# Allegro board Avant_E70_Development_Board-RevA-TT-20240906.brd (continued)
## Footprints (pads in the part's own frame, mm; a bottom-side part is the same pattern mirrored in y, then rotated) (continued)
TP
  round 1.4 hole 0.9: 1(0,0)
TP50
  round 1.524 hole 1.016: 1(0,0)
TP_50
  round 1.524 hole 1.016: 1(0,0)
TPC32
  round 0.813 smd: 1(0,0)
TQFN-14
  rect 0.84x0.3 smd: 1(-1.69,-0.75) 7(1.69,-0.75) 8(1.69,0.75) 14(-1.69,0.75)
  rect 0.3x0.84 smd: 2(-1,-1.69) 3(-0.5,-1.69) 4(0,-1.69) 5(0.5,-1.69) 6(1,-1.69) 9(1,1.69) 10(0.5,1.69) 11(0,1.69) 12(-0.5,1.69) 13(-1,1.69)
  rect 2.15x2.15 smd: 15(0,0)
TQFP64_0P5_12P2X12P2_H1P6
  rect 1.108x0.321 smd: 1(-5.8,3.75) 2(-5.8,3.25) 3(-5.8,2.75) 4(-5.8,2.25) 5(-5.8,1.75) 6(-5.8,1.25) 7(-5.8,0.75) 8(-5.8,0.25) 9(-5.8,-0.25) 10(-5.8,-0.75) 11(-5.8,-1.25) 12(-5.8,-1.75) 13(-5.8,-2.25) 14(-5.8,-2.75) 15(-5.8,-3.25) 16(-5.8,-3.75) 33(5.8,-3.75) 34(5.8,-3.25) 35(5.8,-2.75) 36(5.8,-2.25) 37(5.8,-1.75) 38(5.8,-1.25) 39(5.8,-0.75) 40(5.8,-0.25) 41(5.8,0.25) 42(5.8,0.75) 43(5.8,1.25) 44(5.8,1.75) 45(5.8,2.25) 46(5.8,2.75) 47(5.8,3.25) 48(5.8,3.75)
  rect 0.321x1.108 smd: 17(-3.75,-5.8) 18(-3.25,-5.8) 19(-2.75,-5.8) 20(-2.25,-5.8) 21(-1.75,-5.8) 22(-1.25,-5.8) 23(-0.75,-5.8) 24(-0.25,-5.8) 25(0.25,-5.8) 26(0.75,-5.8) 27(1.25,-5.8) 28(1.75,-5.8) 29(2.25,-5.8) 30(2.75,-5.8) 31(3.25,-5.8) 32(3.75,-5.8) 49(3.75,5.8) 50(3.25,5.8) 51(2.75,5.8) 52(2.25,5.8) 53(1.75,5.8) 54(1.25,5.8) 55(0.75,5.8) 56(0.25,5.8) 57(-0.25,5.8) 58(-0.75,5.8) 59(-1.25,5.8) 60(-1.75,5.8) 61(-2.25,5.8) 62(-2.75,5.8) 63(-3.25,5.8) 64(-3.75,5.8)
TSOT26_AP62201WU-7
  rect 1x0.7 smd: 1(-1.1,0.95) 2(-1.1,0) 3(-1.1,-0.95) 4(1.1,-0.95) 5(1.1,0) 6(1.1,0.95)
TUR_TH
  round 2.54 hole 1.956: 1(0,0)
UDFN6_040
  rect 0.22x0.42 smd: 1(-0.4,-0.325) 2(0,-0.325) 3(0.4,-0.325) 4(0.4,0.325) 5(0,0.325) 6(-0.4,0.325)
unnamed
  round 6.35 hole 4.089 unplated: (0,0)
USB_MINI_B-1734035-2
  round 0.9 hole 0.9 unplated: (-2.2,5.25) (2.2,5.25)
  rect 0.5x2.3 smd: 1(-1.6,7.85) 2(-0.8,7.85) 3(0,7.85) 4(0.8,7.85) 5(1.6,7.85)
  rect 2x2.5 smd: 6(-4.45,7.75) 7(-4.45,2.25) 8(4.45,2.25) 9(4.45,7.75)
USB_TYPEC_RA_SMT
  round 0.65 hole 0.65 unplated: (-3.6,1.04)
  oval 0.95x0.65 hole 0.95x0.65 unplated: (3.6,1.04)
  rect 0.3x0.7 smd: A1(-2.75,1.7) A2(-2.25,1.7) A3(-1.75,1.7) A4(-1.25,1.7) A5(-0.75,1.7) A6(-0.25,1.7) A7(0.25,1.7) A8(0.75,1.7) A9(1.25,1.7) A10(1.75,1.7) A11(2.25,1.7) A12(2.75,1.7) B1(2.5,0) B2(2,0) B3(1.5,0) B4(1,0) B5(0.5,0) B6(0,0) B7(-0.5,0) B8(-1,0) B9(-1.5,0) B10(-2,0) B11(-2.5,0) B12(-3,0)
  oval 1x1.6 hole 0.6x1.2: G1(-4.13,-0.21) G2(4.13,-0.21) G3(-4.49,-6.16) G4(4.49,-6.16)
X4-2520
  rect 1.2x1 smd: 1(-0.85,-0.65) 2(0.85,-0.65) 3(0.85,0.65) 4(-0.85,0.65)
XFDFN6
  rect 0.37x0.24 smd: 1(-0.515,0.4) 2(-0.515,0) 3(-0.515,-0.4) 4(0.515,-0.4) 5(0.515,0) 6(0.515,0.4)
  rect 0.4x1.08 smd: 7(0,0)
XTAL_4P_7M
  rect 1.4x1.2 smd: 1(-1.1,-0.85) 2(1.1,-0.85) 3(1.1,0.85) 4(-1.1,0.85)

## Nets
0V82_EN: R704.2 U45.C7(GPIO2) UNK0V82_EN.1
0V82_MON: R575.2 U45.K8(VMON1)
0V82_MON_GS: R576.2 U45.J8(VMON1GS)
0V82_TRIM: R562.2 U45.D8(TRIM1)
1V8_LDO: C208.1 FB16.1 FB28.1 R189.2 U116.5(VOUT)
1V80_EN: R716.2 U45.E6(GPIO4) UNK1V80_EN.1
1V80_MON: R577.2 U45.C10(VMON5) U45.J7(VMON3)
1V80_TRIM: R287.2 U45.B8(TRIM3)
12V00_MON: R289.1 R554.2 U45.B9(VMON9)
GND: C1.2 C2.2 C3.2 C4.2 C5.2 C6.2 C7.2 C8.2 C9.2 C10.2 C11.2 C12.2 C13.2 C14.2 C15.2 C16.2 C17.1 C18.1 C19.2 C20.2 C21.2 C22.2 C23.1 C24.2 C25.2 C26.2 C27.2 C29.1 C30.1 C31.2 C32.2 C33.2 C34.2 C36.2 C37.2 C38.2 C39.2 C40.2 C41.2 C42.2 C43.2 C44.2 C45.2 C46.2 C47.2 C49.2 C50.2 C51.2 C53.2 C54.2 C55.2 C56.2 C57.2 C58.2 C59.2 C60.2 C61.2 C63.2 C64.2 C65.2 C66.2 C69.2 C94.2 C97.2 C98.2 C99.2 C100.2 C103.2 C104.2 C113.2 C138.1 C139.1 C140.1 C142.2 C143.2 C144.2 C145.2 C146.2 C147.2 C148.2 C149.2 C150.2 C151.2 C152.2 C163.1 C164.2 C165.2 C166.2 C167.2 C168.1 C169.1 C171.2 C172.2 C173.2 C174.2 C175.2 C176.2 C177.2 C178.2 C207.2 C208.2 C287.2 C288.2 C289.2 C290.2 C291.2 C292.2 C293.2 C386.2 C387.2 C388.2 C396.2 C397.2 C398.2 C399.2 C400.2 C401.2 C402.1 C403.1 C404.2 C405.1 C465.2 C466.2 C467.2 C468.2 C469.2 C470.2 C471.2 C472.2 C473.2 C474.2 C475.2 C476.2 C477.2 C478.2 C479.2 C480.2 C481.2 C482.2 C483.2 C484.2 C485.2 C486.2 C487.2 C488.2 C489.2 C490.2 C491.2 C492.2 C493.2 C494.2 C495.2 C496.2 C497.2 C498.2 C499.2 C500.2 C501.2 C502.2 C503.2 C504.2 C505.2 C506.2 C507.2 C508.2 C509.2 C510.2 C511.2 C512.2 C525.2 C526.2 C527.2 C528.2 C529.2 C530.2 C531.2 C532.2 C533.2 C534.2 C535.2 C536.2 C537.2 C538.2 C539.2 C540.2 C541.2 C542.2 C543.2 C544.2 C545.2 C546.2 C547.2 C548.2 C556.2 C557.2 C558.2 C560.2 C561.2 C562.2 C563.2 C565.2 C579.2 C580.2 C584.2 C586.2 C587.2 C588.2 C589.2 C590.2 C591.2 C592.2 C593.2 C594.2 C595.2 C596.2 C597.2 C598.2 C599.2 C600.2 C612.2 C613.2 C614.2 C615.2 C616.2 C617.2 C618.2 C619.2 C620.1 C621.1 C622.2 C623.2 C625.2 C626.2 C628.2 C629.2 C630.2 C631.2 C632.2 C635.2 C636.2 C637.2 C639.2 C640.2 C641.2 C642.2 C643.2 C644.2 C646.2 C647.2 C648.2 C650.2 C651.2 C652.2 C654.2 C655.2 C656.2 C659.2 C660.2 C661.2 C663.2 C664.2 C665.2 C672.2 C673.2 C675.2 C676.2 C677.1 C713.2 C714.2 C717.2 C718.2 C719.2 C720.2 C721.2 C722.2 C723.2 C724.2 C725.2 C726.2 C727.2 C728.2 C729.2 C732.2 C733.2 C734.2 C1177.2 C1178.2 C1179.2 C1180.2 C1182.2 C1183.2 C1184.2 C1185.2 C1186.2 C1187.2 C1188.2 C1189.2 C1190.2 C1191.2 C1192.1 C1193.2 C1194.2 C1195.2 C1196.2 C1198.2 C1199.2 C1204.2 C1205.2 C1206.2 C1207.2 C1208.2 C1209.2 C1210.2 C1211.2 C1214.2 C1215.2 C1216.2 C1217.2 C1218.2 C1219.1 C1220.1 C1221.2 C1222.2 C1223.2 C1224.2 C1225.2 C1226.2 C1227.2 C1228.2 C1229.2 C1230.2 C1231.2 C1232.2 C1233.2 C1234.2 C1235.2 C1236.2 C1237.2 C1238.2 C1239.2 C1240.2 C1241.2 C1242.2 C1243.2 C1244.2 C1245.2 C1246.2 C1247.2 C1248.2 C1249.2 C1250.2 C1251.2 C1252.2 C1253.2 C1254.2 C1255.2 C1256.2 C1257.2 C1258.2 C1259.2 C1260.2 C1261.2 C1264.2 C1265.2 C1266.2 C1267.2 C1268.2 C1269.2 C1647.2 C1648.2 C1649.2 C1650.2 C1651.2 C1652.2 C1653.2 C1654.2 C1655.2 C1656.2 C1657.2 C1658.2 C1659.2 C1660.2 C1661.2 C1662.2 C1663.2 C1668.2 D1.K(CATHODE) D3.1(GND) D52.A1(ANODE1) D52.A2(ANODE2) D62.K D73.K D74.K D78.K GND1.1(TP) GND2.1(TP) GND3.1(TP) GND4.1(TP) GND5.1(TP) GND6.1(TP) GND7.1(TP) GND8.1(TP) GND9.1(TP) GND10.1(TP) GND11.1(TP) GND12.1(TP) GND13.1(TP) GND14.1(TP) GND15.1(TP) J1.7 J2.5(GND) J2.6(CASE#6) J2.7(CASE#7) J2.8(CASE#8) J2.9(CASE#9) J3.13 J3.14 J6.5 J6.11 J7.5 J7.11 J8.3 J10.11 J10.12 J25.A1(GND1) J25.A12(GND2) J25.B1(GND4) J25.B12(GND3) J25.G1(PGND1) J25.G2(PGND2) J25.G3(PGND3) J25.G4(PGND4) J31.1 J32.1 J33.1 J39.7 J48.A1(GND#A1) J48.A4(GND#A4) J48.A5(GND#A5) J48.A8(GND#A8) J48.A9(GND#A9) J48.A12(GND#A12) J48.A13(GND#A13) J48.A16(GND#A16) J48.A17(GND#A17) J48.A20(GND#A20) J48.A21(GND#A21) J48.A24(GND#A24) J48.A25(GND#A25) J48.A28(GND#A28) J48.A29(GND#A29) J48.A32(GND#A32) J48.A33(GND#A33) J48.A36(GND#A36) J48.A37(GND#A37) J48.A40(GND#A40) J48.B2(GND#B2) J48.B3(GND#B3) J48.B6(GND#B6) J48.B7(GND#B7) J48.B10(GND#B10) J48.B11(GND#B11) J48.B14(GND#B14) J48.B15(GND#B15) J48.B18(GND#B18) J48.B19(GND#B19) J48.B22(GND#B22) J48.B23(GND#B23) J48.B26(GND#B26) J48.B27(GND#B27) J48.B30(GND#B30) J48.B31(GND#B31) J48.B34(GND#B34) J48.B35(GND#B35) J48.B38(GND#B38) J48.B39(GND#B39) J48.C1(GND#C1) J48.C4(GND#C4) J48.C5(GND#C5) J48.C8(GND#C8) J48.C9(GND#C9) J48.C12(GND#C12) J48.C13(GND#C13) J48.C16(GND#C16) J48.C17(GND#C17) J48.C20(GND#C20) J48.C21(GND#C21) J48.C24(GND#C24) J48.C25(GND#C25) J48.C28(GND#C28) J48.C29(GND#C29) J48.C32(GND#C32) J48.C33(GND#C33) J48.C36(GND#C36) J48.C38(GND#C38) J48.C40(GND#C40) J48.D2(GND#D2) J48.D3(GND#D3) J48.D6(GND#D6) J48.D7(GND#D7) J48.D10(GND#D10) J48.D13(GND#D13) J48.D16(GND#D16) J48.D19(GND#D19) J48.D22(GND#D22) J48.D25(GND#D25) J48.D28(GND#D28) J48.D37(GND#D37) J48.D39(GND#D39) J48.E1(GND#E1) J48.E4(GND#E4) J48.E5(GND#E5) J48.E8(GND#E8) J48.E11(GND#E11) J48.E14(GND#E14) J48.E17(GND#E17) J48.E20(GND#E20) J48.E23(GND#E23) J48.E26(GND#E26) J48.E29(GND#E29) J48.E32(GND#E32) J48.E35(GND#E35) J48.E38(GND#E38) J48.E40(GND#E40) J48.F2(GND#F2) J48.F3(GND#F3) J48.F6(GND#F6) J48.F9(GND#F9) J48.F12(GND#F12) J48.F15(GND#F15) J48.F18(GND#F18) J48.F21(GND#F21) J48.F24(GND#F24) J48.F27(GND#F27) J48.F30(GND#F30) J48.F33(GND#F33) J48.F36(GND#F36) J48.F39(GND#F39) J48.G1(GND#G1) J48.G4(GND#G4) J48.G5(GND#G5) J48.G8(GND#G8) J48.G11(GND#G11) J48.G14(GND#G14) J48.G17(GND#G17) J48.G20(GND#G20) J48.G23(GND#G23) J48.G26(GND#G26) J48.G29(GND#G29) J48.G32(GND#G32) J48.G35(GND#G35) J48.G38(GND#G38) J48.G40(GND#G40) J48.H3(GND#H3) J48.H6(GND#H6) J48.H9(GND#H9) J48.H12(GND#H12) J48.H15(GND#H15) J48.H18(GND#H18) J48.H21(GND#H21) J48.H24(GND#H24) J48.H27(GND#H27) J48.H30(GND#H30) J48.H33(GND#H33) J48.H36(GND#H36) J48.H39(GND#H39) J48.J1(GND#J1) J48.J4(GND#J4) J48.J5(GND#J5) J48.J8(GND#J8) J48.J11(GND#J11) J48.J14(GND#J14) J48.J17(GND#J17) J48.J20(GND#J20) J48.J23(GND#J23) J48.J26(GND#J26) J48.J29(GND#J29) J48.J32(GND#J32) J48.J35(GND#J35) J48.J38(GND#J38) J48.J40(GND#J40) J48.K2(GND#K2) J48.K3(GND#K3) J48.K6(GND#K6) J48.K9(GND#K9) J48.K12(GND#K12) J48.K15(GND#K15) J48.K18(GND#K18) J48.K21(GND#K21) J48.K24(GND#K24) J48.K27(GND#K27) J48.K30(GND#K30) J48.K33(GND#K33) J48.K36(GND#K36) J48.K39(GND#K39) J50.2(GND#2) J50.3(GND#3) J53.11 J53.12 J54.A1(GND#A1) J54.A4(GND#A4) J54.A5(GND#A5) J54.A8(GND#A8) J54.A9(GND#A9) J54.A12(GND#A12) J54.A13(GND#A13) J54.A16(GND#A16) J54.A17(GND#A17) J54.A20(GND#A20) J54.A21(GND#A21) J54.A24(GND#A24) J54.A25(GND#A25) J54.A28(GND#A28) J54.A29(GND#A29) J54.A32(GND#A32) J54.A33(GND#A33) J54.A36(GND#A36) J54.A37(GND#A37) J54.A40(GND#A40) J54.B2(GND#B2) J54.B3(GND#B3) J54.B6(GND#B6) J54.B7(GND#B7) J54.B10(GND#B10) J54.B11(GND#B11) J54.B14(GND#B14) J54.B15(GND#B15) J54.B18(GND#B18) J54.B19(GND#B19) J54.B22(GND#B22) J54.B23(GND#B23) J54.B26(GND#B26) J54.B27(GND#B27) J54.B30(GND#B30) J54.B31(GND#B31) J54.B34(GND#B34) J54.B35(GND#B35) J54.B38(GND#B38) J54.B39(GND#B39) J54.C1(GND#C1) J54.C4(GND#C4) J54.C5(GND#C5) J54.C8(GND#C8) J54.C9(GND#C9) J54.C12(GND#C12) J54.C13(GND#C13) J54.C16(GND#C16) J54.C17(GND#C17) J54.C20(GND#C20) J54.C21(GND#C21) J54.C24(GND#C24) J54.C25(GND#C25) J54.C28(GND#C28) J54.C29(GND#C29) J54.C32(GND#C32) J54.C33(GND#C33) J54.C36(GND#C36) J54.C38(GND#C38) J54.C40(GND#C40) J54.D2(GND#D2) J54.D3(GND#D3) J54.D6(GND#D6) J54.D7(GND#D7) J54.D10(GND#D10) J54.D13(GND#D13) J54.D16(GND#D16) J54.D19(GND#D19) J54.D22(GND#D22) J54.D25(GND#D25) J54.D28(GND#D28) J54.D37(GND#D37) J54.D39(GND#D39) J54.E1(GND#E1) J54.E4(GND#E4) J54.E5(GND#E5) J54.E8(GND#E8) J54.E11(GND#E11) J54.E14(GND#E14) J54.E17(GND#E17) J54.E20(GND#E20) J54.E23(GND#E23) J54.E26(GND#E26) J54.E29(GND#E29) J54.E32(GND#E32) J54.E35(GND#E35) J54.E38(GND#E38) J54.E40(GND#E40) J54.F2(GND#F2) J54.F3(GND#F3) J54.F6(GND#F6) J54.F9(GND#F9) J54.F12(GND#F12) J54.F15(GND#F15) J54.F18(GND#F18) J54.F21(GND#F21) J54.F24(GND#F24) J54.F27(GND#F27) J54.F30(GND#F30) J54.F33(GND#F33) J54.F36(GND#F36) J54.F39(GND#F39) J54.G1(GND#G1) J54.G4(GND#G4) J54.G5(GND#G5) J54.G8(GND#G8) J54.G11(GND#G11) J54.G14(GND#G14) J54.G17(GND#G17) J54.G20(GND#G20) J54.G23(GND#G23) J54.G26(GND#G26) J54.G29(GND#G29) J54.G32(GND#G32) J54.G35(GND#G35) J54.G38(GND#G38) J54.G40(GND#G40) J54.H3(GND#H3) J54.H6(GND#H6) J54.H9(GND#H9) J54.H12(GND#H12) J54.H15(GND#H15) J54.H18(GND#H18) J54.H21(GND#H21) J54.H24(GND#H24) J54.H27(GND#H27) J54.H30(GND#H30) J54.H33(GND#H33) J54.H36(GND#H36) J54.H39(GND#H39) J54.J1(GND#J1) J54.J4(GND#J4) J54.J5(GND#J5) J54.J8(GND#J8) J54.J11(GND#J11) J54.J14(GND#J14) J54.J17(GND#J17) J54.J20(GND#J20) J54.J23(GND#J23) J54.J26(GND#J26) J54.J29(GND#J29) J54.J32(GND#J32) J54.J35(GND#J35) J54.J38(GND#J38) J54.J40(GND#J40) J54.K2(GND#K2) J54.K3(GND#K3) J54.K6(GND#K6) J54.K9(GND#K9) J54.K12(GND#K12) J54.K15(GND#K15) J54.K18(GND#K18) J54.K21(GND#K21) J54.K24(GND#K24) J54.K27(GND#K27) J54.K30(GND#K30) J54.K33(GND#K33) J54.K36(GND#K36) J54.K39(GND#K39) J81.1 J83.13 JP3.2 JP15.1 JP17.2 JP26.6 JP26.9 JP26.14 JP26.20 JP26.25 JP26.30 JP26.34 JP26.39 JP64.2 Q1.E(EMITTER) Q2.E Q3.E Q4.E Q7.E Q8.E Q9.E Q10.E Q11.E Q12.E Q13.E Q14.E Q15.E Q16.E Q17.E Q18.E Q19.E Q20.E Q21.E Q22.E Q23.E Q24.E Q26.S Q27.E Q28.E Q29.E Q30.E Q31.E Q32.E Q33.E Q34.E R5.2 R15.1 R54.1 R77.2 R92.2 R95.1 R100.2 R180.2 R192.1 R232.2 R234.2 R245.2 R251.1 R252.1 R306.2 R307.1 R317.2 R325.1 R326.1 R340.2 R342.2 R344.2 R398.2 R401.1 R406.1 R413.2 R415.2 R419.2 R421.2 R424.2 R429.2 R430.2 R435.2 R436.2 R440.2 R442.2 R449.2 R451.2 R455.2 R457.2 R465.2 R466.1 R493.1 R545.2 R548.1 R554.1 R568.2 R569.2 R576.1 R583.1 R589.2 R596.2 R597.1 R598.1 R611.1 R612.1 R613.1 R614.1 R616.1 R617.1 R620.2 R621.2 R625.2 R629.2 R639.1 R641.2 R642.2 R643.2 R644.1 R645.1 R651.2 R652.2 R653.2 R654.2 R655.2 R656.2 R663.2 R664.2 R665.2 R666.2 R667.2 R668.2 R669.1 R670.1 R671.1 R672.1 R673.1 R674.1 R681.1 R686.2 R696.2 R697.2 R703.1 SW1.1(A1) SW1.3(A2) SW2.1(A1) SW2.3(A2) SW3.9(B8) SW3.10(B7) SW3.11(B6) SW3.12(B5) SW3.13(B4) SW3.14(B3) SW3.15(B2) SW3.16(B1) SW4.1(A1) SW4.3(A2) SW5.1(A1) SW5.3(A2) SW8.1(A1) SW8.3(A2) U1.1(GND#1) U1.5(GND#5) U1.10(AGND) U1.11(GND#11) U1.13(TEST) U1.15(GND#15) U1.25(GND#25) U1.35(GND#35) U1.47(GND#47) U1.51(GND#51) U2.5(VSS) U3.A1(VSS#A1) U3.A2(VSS#A2) U3.A3(VSS#A3) U3.A4(VSS#A4) U3.A7(VSS#A7) U3.A10(VSS#A10) U3.A13(VSS#A13) U3.A16(VSS#A16) U3.A19(VSS#A19) U3.A22(VSS#A22) U3.A25(VSS#A25) U3.A28(VSS#A28) U3.A31(VSS#A31) U3.A34(VSS#A34) U3.AA6(VSS#AA6) U3.AB2(VSS#AB2) U3.AB8(VSS#AB8) U3.AB11(VSS#AB11) U3.AB23(VSS#AB23) U3.AC18(VSS#AC18) U3.AC22(VSS#AC22) U3.AC32(VSS#AC32) U3.AD13(VSS#AD13) U3.AD25(VSS#AD25) U3.AD28(VSS#AD28) U3.AE16(VSS#AE16) U3.AF8(VSS#AF8) U3.AG3(VSS#AG3) U3.AG22(VSS#AG22) U3.AH11(VSS#AH11) U3.AH19(VSS#AH19) U3.AH28(VSS#AH28) U3.AH32(VSS#AH32) U3.AJ8(VSS#AJ8) U3.AJ14(VSS#AJ14) U3.AJ25(VSS#AJ25) U3.AL3(VSS#AL3) U3.AL32(VSS#AL32) U3.AM7(VSS#AM7) U3.AM12(VSS#AM12) U3.AM15(VSS#AM15) U3.AM19(VSS#AM19) U3.AM22(VSS#AM22) U3.AN27(VSS#AN27) U3.AP1(VSS#AP1) U3.AP34(VSS#AP34) U3.B2(VSS#B2) U3.B4(VSS#B4) U3.B5(VSS#B5) U3.B6(VSS#B6) U3.B7(VSSR#B7) U3.B8(VSS#B8) U3.B9(VSS#B9) U3.B10(VSSR#B10) U3.B11(VSS#B11) U3.B12(VSS#B12) U3.B13(VSSR#B13) U3.B14(VSS#B14) U3.B15(VSS#B15) U3.B16(VSSR#B16) U3.B17(VSS#B17) U3.B18(VSS#B18) U3.B19(VSSR#B19) U3.B20(VSS#B20) U3.B21(VSS#B21) U3.B22(VSSR#B22) U3.B23(VSS#B23) U3.B24(VSS#B24) U3.B25(VSSR#B25) U3.B26(VSS#B26) U3.B27(VSS#B27) U3.B28(VSSR#B28) U3.B29(VSS#B29) U3.B30(VSS#B30) U3.B31(VSSR#B31) U3.B32(VSS#B32) U3.B33(VSS#B33) U3.B34(VSSR#B34) U3.C2(VSS#C2) U3.C4(VSS#C4) U3.C7(VSS#C7) U3.C10(VSS#C10) U3.C13(VSS#C13) U3.C16(VSS#C16) U3.C19(VSS#C19) U3.C22(VSS#C22) U3.C25(VSS#C25) U3.C28(VSS#C28) U3.C31(VSS#C31) U3.C34(VSS#C34) U3.D1(VSS#D1) U3.D2(VSSR#D2) U3.D3(VSS#D3) U3.D4(VSSR#D4) U3.D5(VSS#D5) U3.D6(VSS#D6) U3.D7(VSSR#D7) U3.D8(VSS#D8) U3.D9(VSS#D9) U3.D10(VSSR#D10) U3.D11(VSS#D11) U3.D12(VSS#D12) U3.D13(VSSR#D13) U3.D14(VSS#D14) U3.D15(VSS#D15) U3.D16(VSSR#D16) U3.D17(VSS#D17) U3.D18(VSS#D18) U3.D19(VSSR#D19) U3.D20(VSS#D20) U3.D21(VSS#D21) U3.D22(VSSR#D22) U3.D23(VSS#D23) U3.D24(VSS#D24) U3.D25(VSSR#D25) U3.D26(VSS#D26) U3.D27(VSS#D27) U3.D28(VSSR#D28) U3.D29(VSS#D29) U3.D30(VSS#D30) U3.D31(VSSR#D31) U3.D32(VSS#D32) U3.D33(VSS#D33) U3.D34(VSSR#D34) U3.E2(VSS#E2) U3.E4(VSS#E4) U3.E7(VSS#E7) U3.E10(VSS#E10) U3.E13(VSS#E13) U3.E16(VSS#E16) U3.E19(VSS#E19) U3.E22(VSS#E22) U3.E25(VSS#E25) U3.E28(VSS#E28) U3.E31(VSS#E31) U3.E34(VSS#E34) U3.F2(VSS#F2) U3.F4(VSS#F4) U3.F5(VSS#F5) U3.F6(VSS#F6) U3.F7(VCCJB#F7) U3.F8(VSS#F8) U3.F9(VSS#F9) U3.F10(VCCJB#F10) U3.F11(VSS#F11) U3.F12(VSS#F12) U3.F13(VCCJB#F13) U3.F14(VSS#F14) U3.F15(VSS#F15) U3.F16(VCCJB#F16) U3.F17(VSS#F17) U3.F18(VSS#F18) U3.F19(VCCJB#F19) U3.F20(VSS#F20) U3.F21(VSS#F21) U3.F22(VCCJB#F22) U3.F23(VSS#F23) U3.F24(VSS#F24) U3.F25(VCCJB#F25) U3.F26(VSS#F26) U3.F27(VSS#F27) U3.F28(VCCJB#F28) U3.F29(VSS#F29) U3.F30(VSS#F30) U3.F31(VCCJB#F31) U3.F32(VSS#F32) U3.F33(VSS#F33) U3.F34(VCCJB#F34) U3.G1(VSS#G1) U3.G2(VSSR#G2) U3.G3(VSS#G3) U3.G4(VSSR#G4) U3.G7(VSS#G7) U3.G10(VSS#G10) U3.G13(VSS#G13) U3.G16(VSS#G16) U3.G19(VSS#G19) U3.G22(VSS#G22) U3.G25(VSS#G25) U3.G28(VSS#G28) U3.G31(VSS#G31) U3.G34(VSS#G34) U3.H2(VSS#H2) U3.H4(VSS#H4) U3.H5(VSS#H5) U3.H6(VSS#H6) U3.H7(VCCJB#H7) U3.H8(VSS#H8) U3.H9(VSS#H9) U3.H10(VCCJB#H10) U3.H11(VSS#H11) U3.H12(VSS#H12) U3.H13(VCCJB#H13) U3.H14(VSS#H14) U3.H15(VSS#H15) U3.H16(VCCJB#H16) U3.H17(VSS#H17) U3.H18(VSS#H18) U3.H19(VCCJB#H19) U3.H20(VSS#H20) U3.H21(VSS#H21) U3.H22(VCCJB#H22) U3.H23(VSS#H23) U3.H24(VSS#H24) U3.H25(VCCJB#H25) U3.H26(VSS#H26) U3.H27(VSS#H27) U3.H28(VCCJB#H28) U3.H29(VSS#H29) U3.H30(VSS#H30) U3.H31(VCCJB#H31) U3.H32(VSS#H32) U3.H33(VSS#H33) U3.H34(VCCJB#H34) U3.J2(VSS#J2) U3.J4(VSS#J4) U3.J5(VSS#J5) U3.J7(VSS#J7) U3.J8(VSSR#J8) U3.J9(VSSR#J9) U3.J10(VSS#J10) U3.J11(VSSR#J11) U3.J13(VSS#J13) U3.J14(VSSR#J14) U3.J15(VSSR#J15) U3.J16(VSS#J16) U3.J17(VCCJB#J17) U3.J19(VSS#J19) U3.J20(VSSR#J20) U3.J21(VSSR#J21) U3.J22(VSS#J22) U3.J23(VSS#J23) U3.J25(VSS#J25) U3.J26(VSSR#J26) U3.J27(VSSR#J27) U3.J28(VSS#J28) U3.J29(VSSR#J29) U3.J31(VSS#J31) U3.J32(VSSR#J32) U3.J33(VSSR#J33) U3.J34(VSS#J34) U3.K1(VSS#K1) U3.K2(VCCJB#K2) U3.K3(VSS#K3) U3.K4(VCCJB#K4) U3.K5(VSSR#K5) U3.K6(VSS#K6) U3.K7(VSSR#K7) U3.K8(VSS#K8) U3.K9(VSS#K9) U3.K10(VCCJB#K10) U3.K11(VSS#K11) U3.K12(VCCJB#K12) U3.K13(VCCJB#K13) U3.K14(VSS#K14) U3.K15(VSS#K15) U3.K16(VCCJB#K16) U3.K17(VSS#K17) U3.K18(VSS#K18) U3.K19(VSSR#K19) U3.K20(VSS#K20) U3.K21(VSS#K21) U3.K22(VCCJB#K22) U3.K23(VSS#K23) U3.K24(VSS#K24) U3.K25(VCCJB#K25) U3.K26(VSS#K26) U3.K27(VSS#K27) U3.K28(VSS#K28) U3.K29(VCCJB#K29) U3.K30(VSS#K30) U3.K31(VSS#K31) U3.K32(VSS#K32) U3.K33(VSS#K33) U3.K34(VSS#K34) U3.L2(VSS#L2) U3.L4(VSS#L4) U3.L5(VSSR#L5) U3.L6(VCCJB#L6) U3.L13(VSSR#L13) U3.L14(VSSR#L14) U3.L15(VSSR#L15) U3.L16(VCCJB#L16) U3.L17(VSSR#L17) U3.L18(VCCJB#L18) U3.L19(VSS#L19) U3.L20(VCCJB#L20) U3.L21(VSS#L21) U3.L22(VSSR#L22) U3.L23(VSS#L23) U3.L24(VSSR#L24) U3.L25(VSS#L25) U3.L27(VSS#L27) U3.L29(VSS#L29) U3.L31(VSS#L31) U3.L33(VSS#L33) U3.M2(VSS#M2) U3.M4(VSS#M4) U3.M5(VSS#M5) U3.M11(VSS#M11) U3.M15(VSS#M15) U3.M17(VSS#M17) U3.M18(VSS#M18) U3.M21(VCCJB#M21) U3.M22(VSS#M22) U3.M23(VCCJB#M23) U3.M24(VSS#M24) U3.M25(VCCJB#M25) U3.M26(VSS#M26) U3.M27(VSS#M27) U3.M29(VSS#M29) U3.M31(VSS#M31) U3.M33(VSS#M33) U3.N1(VSS#N1) U3.N2(VCCJB#N2) U3.N3(VSS#N3) U3.N4(VCCJB#N4) U3.N9(VSS#N9) U3.N13(VSS#N13) U3.N23(VSS#N23) U3.N25(VSS#N25) U3.N26(VSSR#N26) U3.N27(VCCJB#N27) U3.N28(VSS#N28) U3.N29(VCCJB#N29) U3.N30(VSS#N30) U3.N31(VSSR#N31) U3.N32(VSS#N32) U3.N33(VSSR#N33) U3.N34(VSS#N34) U3.P17(VSS#P17) U3.P22(VSS#P22) U3.P23(VSSR#P23) U3.P24(VSS#P24) U3.P25(VCCJB#P25) U3.P26(VSSR#P26) U3.P27(VSS#P27) U3.P29(VSS#P29) U3.P31(VSS#P31) U3.P33(VSS#P33) U3.R21(VSS#R21) U3.R23(VSS#R23) U3.R25(VSS#R25) U3.R26(VSS#R26) U3.R27(VSS#R27) U3.R29(VSS#R29) U3.R31(VSS#R31) U3.R33(VSS#R33) U3.T2(VSS#T2) U3.T4(VSS#T4) U3.T17(VSS#T17) U3.T21(VSS#T21) U3.T23(VSS#T23) U3.T27(VCCJB#T27) U3.T28(VSS#T28) U3.T29(VCCJB#T29) U3.T30(VSS#T30) U3.T31(VSSR#T31) U3.T32(VSS#T32) U3.T33(VSSR#T33) U3.T34(VSS#T34) U3.U10(VSS#U10) U3.U14(VSS#U14) U3.U18(VSS#U18) U3.U20(VSS#U20) U3.V6(VSS#V6) U3.V18(VSS#V18) U3.V20(VSS#V20) U3.V24(VSS#V24) U3.W3(VSS#W3) U3.W16(VSS#W16) U3.W19(VSS#W19) U3.W21(VSS#W21) U3.W28(VSS#W28) U3.W32(VSS#W32) U3.Y13(VSS#Y13) U3.Y23(VSS#Y23) U3.Y25(VSS#Y25) U4.4(GND) U4.9(EPAD) U5.A3(VSS_A3) U5.A10(VSS_A10) U5.AB3(VSS_AB3) U5.AB5(VSS_AB5) U5.AB8(VSS_AB8) U5.AB10(VSS_AB10) U5.C1(VSS_C1) U5.C5(VSS_C5) U5.C8(VSS_C8) U5.C12(VSS_C12) U5.D2(VSS_D2) U5.D4(VSS_D4) U5.D9(VSS_D9) U5.D11(VSS_D11) U5.E1(VSS_E1) U5.E5(VSS_E5) U5.E8(VSS_E8) U5.E12(VSS_E12) U5.G1(VSS_G1) U5.G3(VSS_G3) U5.G5(VSS_G5) U5.G8(VSS_G8) U5.G10(VSS_G10) U5.G12(VSS_G12) U5.J1(VSS_J1) U5.J3(VSS_J3) U5.J10(VSS_J10) U5.J12(VSS_J12) U5.K2(VSS_K2) U5.K4(VSS_K4) U5.K9(VSS_K9) U5.K11(VSS_K11) U5.N2(VSS_N2) U5.N4(VSS_N4) U5.N9(VSS_N9) U5.N11(VSS_N11) U5.P1(VSS_P1) U5.P3(VSS_P3) U5.P10(VSS_P10) U5.P12(VSS_P12) U5.T1(VSS_T1) U5.T3(VSS_T3) U5.T5(VSS_T5) U5.T8(VSS_T8) U5.T10(VSS_T10) U5.T12(VSS_T12) U5.V1(VSS_V1) U5.V5(VSS_V5) U5.V8(VSS_V8) U5.V12(VSS_V12) U5.W2(VSS_W2) U5.W4(VSS_W4) U5.W9(VSS_W9) U5.W11(VSS_W11) U5.Y1(VSS_Y1) U5.Y5(VSS_Y5) U5.Y8(VSS_Y8) U5.Y12(VSS_Y12) U6.5(GND) U6.9(EPAD) U17.1(GND) U32.5(GND) U32.9(EPAD) U34.1(GND) U35.1(GND) U36.1(GND) U37.1(GND) U38.1(GND) U39.1(GND) U40.1(GND) U41.1(GND) U43.2(GND#2) U43.3(GND#3) U43.15(EPAD) U44.5(GND) U44.7(EPAD) U45.A1(GND#A1) U45.A10(GND#A10) U45.D10(VMON4GS) U45.E2(GND#E2) U45.E7(GND#E7) U45.F7(GND#F7) U45.F9(GND#F9) U45.G4(GND#G4) U45.K1(GND#K1) U45.K6(I2C_ADDR) U45.K7(VMON3GS) U45.K10(GND#K10) U46.7(GND) U107.1(GND) U108.11(GND) U108.25(EPAD) U109.3 U109.6 U110.7(PGND_1) U110.8(PGND_2) U110.11(PGND_3) U110.12(PGND_4) U110.21(AGND) U111.7(PGND_1) U111.8(PGND_2) U111.11(PGND_3) U111.12(PGND_4) U111.21(AGND) U114.3(GND) U114.4(AGND) U115.3(GND) U115.4(AGND) U116.2(GND) U118.3(GND) U118.7(EPAD) U119.A3(VSS_A3) U119.A10(VSS_A10) U119.AB3(VSS_AB3) U119.AB5(VSS_AB5) U119.AB8(VSS_AB8) U119.AB10(VSS_AB10) U119.C1(VSS_C1) U119.C5(VSS_C5) U119.C8(VSS_C8) U119.C12(VSS_C12) U119.D2(VSS_D2) U119.D4(VSS_D4) U119.D9(VSS_D9) U119.D11(VSS_D11) U119.E1(VSS_E1) U119.E5(VSS_E5) U119.E8(VSS_E8) U119.E12(VSS_E12) U119.G1(VSS_G1) U119.G3(VSS_G3) U119.G5(VSS_G5) U119.G8(VSS_G8) U119.G10(VSS_G10) U119.G12(VSS_G12) U119.J1(VSS_J1) U119.J3(VSS_J3) U119.J10(VSS_J10) U119.J12(VSS_J12) U119.K2(VSS_K2) U119.K4(VSS_K4) U119.K9(VSS_K9) U119.K11(VSS_K11) U119.N2(VSS_N2) U119.N4(VSS_N4) U119.N9(VSS_N9) U119.N11(VSS_N11) U119.P1(VSS_P1) U119.P3(VSS_P3) U119.P10(VSS_P10) U119.P12(VSS_P12) U119.T1(VSS_T1) U119.T3(VSS_T3) U119.T5(VSS_T5) U119.T8(VSS_T8) U119.T10(VSS_T10) U119.T12(VSS_T12) U119.V1(VSS_V1) U119.V5(VSS_V5) U119.V8(VSS_V8) U119.V12(VSS_V12) U119.W2(VSS_W2) U119.W4(VSS_W4) U119.W9(VSS_W9) U119.W11(VSS_W11) U119.Y1(VSS_Y1) U119.Y5(VSS_Y5) U119.Y8(VSS_Y8) U119.Y12(VSS_Y12) U120.1(GND#1) U120.12(GND#12) U120.13(GND#13) U120.20(VOSNS-) U120.22(AGND) U120.29(GND#29) X1.2(G1) X1.4(G2) X3.2(GND) Y1.3(GND)
VBUS_5V00: C8.1 D3.6(VBUS) FB2.1 R1.2
VCC_0V82: C1645.1 C1653.1 C1654.1 C1655.1 C1656.1 C1657.1 C1658.1 C1659.1 C1660.1 C1661.1 C1662.1 J73.1 R474.2 R658.3(I1) U120.11(VOUT#11) U120.15(VOUT#15) UNK0V82.1
VCC_0V82_ALTN: R693.2 U120.5(ALT)
VCC_0V82_PG: R705.2 U120.7(PG)
VCC_0V82_SENSE+: C62.1 C1645.2 R561.1 R697.1 R698.1 U120.21(VOSNS+)
VCC_0V90: C659.1 C660.1 JP31.1 L19.2 R446.2 R450.1 UNK0V9.1
VCC_1V00: C386.1 C387.1 JP32.1 L8.2 R229.2 R231.1 UNK1V.1
VCC_1V10: C639.1 C640.1 FB29.1 JP33.1 L15.2 R416.2 R420.1 R492.2 UNK1V1.1
VCC_1V20: C646.1 C647.1 C718.1 JP47.1 JP58.1 JP59.1 JP60.1 JP61.1 JP62.1 L16.2 R431.1 R432.2 R556.1 U44.6(IN) UNK1V2.1
VCC_1V35: C663.1 C664.1 JP34.1 L20.2 R452.2 R456.1 UNK1V35.1
VCC_1V50: C654.1 C655.1 JP35.1 L18.2 R443.2 R445.1 R714.2 UNK1V5.1
VCC_1V80: C642.1 C643.1 JP36.1 JP48.1 JP69.1 JP71.1 JP73.1 JP75.1 JP77.1 L5.2 R425.1 R426.2 R577.1 R578.1 UNK1V8.1
VCC_1V80_FT: C11.1 C12.1 C13.1 C14.1 C15.1 U1.12(VCORE#12) U1.37(VCORE#37) U1.49(VREGOUT) U1.64(VCORE#64)
VCC_2V50: C207.1 C650.1 C651.1 JP49.1 L17.2 R185.1 R437.1 R438.2 U116.4(VDD) UNK2V5.1
VCC_3V30: C1.1 C2.1 C3.1 C4.1 C5.1 C16.1 C632.1 C635.1 C636.1 C720.1 C733.1 FB1.2 FB3.2 J1.1 J10.1 J10.2 J53.1 J53.2 J58.1 J63.1 J64.1 JP12.1 JP50.1 L4.2 R2.1 R3.1 R4.1 R11.2 R12.1 R13.1 R14.1 R16.2 R17.2 R62.2 R63.2 R83.2 R84.2 R85.2 R86.2 R87.2 R90.2 R91.2 R139.1 R169.2 R217.2 R310.2 R314.2 R315.2 R316.2 R321.2 R322.2 R327.2 R328.2 R391.1 R395.1 R411.2 R414.1 R417.2 R427.2 R433.2 R439.2 R444.2 R447.2 R453.2 R475.2 R521.2 R523.2 R524.2 R526.2 R528.2 R529.2 R532.2 R533.2 R536.2 R546.2 R657.2 R680.2 R702.1 U1.20(VCCIO#20) U1.31(VCCIO#31) U1.42(VCCIO#42) U1.50(VREGIN) U1.56(VCCIO#56) U2.6(ORG) U2.8(VCC) U44.4(BIAS) U46.14(VCCB) UNK3V3.1 Y1.1(E/D) Y1.6(VDD)
VCC_3V30_EN: R682.1 U45.F6(GPIO5) VCC_3V30_EN.1(TP)
VCC_3V30_MON: R680.1 R681.2 U45.B10(VMON6)
VCC_5V00: C59.1 C388.1 C637.1 C641.1 C644.1 C648.1 C652.1 C656.1 C661.1 C665.1 C675.1 C676.1 C1647.1 C1648.1 C1649.1 C1650.1 C1651.1 C1652.1 JP13.1 L21.2 R233.1 R412.1 R418.1 R428.1 R434.1 R441.1 R448.1 R454.1 R464.1 R467.1 R510.1 R572.1 U17.3(VIN) U34.3(VIN) U35.3(VIN) U36.3(VIN) U37.3(VIN) U38.3(VIN) U39.3(VIN) U40.3(VIN) U41.3(VIN) U120.14(VIN#14) U120.26(VIN#26) UNK5V.1
VCC_12V00: C45.1 C46.1 C47.1 C97.1 C98.1 C99.1 C558.1 C560.1 C561.1 C623.1 C625.1 C626.1 C1216.1 C1218.1 D52.K D77.A1(ANODE1) D77.A2(ANODE2) J48.C35(12P0V#C35) J48.C37(12P0V#C37) J54.C35(12P0V#C35) J54.C37(12P0V#C37) J84.2 J84.5 R289.2 R624.2 R628.2 U6.1(EN) U6.8(VIN) U32.1(EN) U32.8(VIN) U114.1(VIN) U115.1(VIN) UNK12V.1
VCC_AUX: C396.1 C397.1 C398.1 C399.1 C400.1 C401.1 J76.1 R154.1 U3.P11(VCCAUXA) U3.W18(VCCAUX#W18) U3.Y12(VCCAUX#Y12) U3.Y22(VCCAUX#Y22) VCCAUX.1(TP)
VCC_AUX_IN: FB16.2 J76.2 R154.2
VCC_CORE: C62.2 C138.2 C139.2 C140.2 C142.1 C143.1 C144.1 C145.1 C146.1 C147.1 C148.1 C149.1 C150.1 C151.1 C152.1 C163.2 C164.1 C165.1 C166.1 C167.1 C168.2 C169.2 C171.1 C172.1 C173.1 C174.1 C175.1 C176.1 C177.1 C178.1 C402.2 C403.2 C404.1 C405.2 C612.1 C613.1 J73.2 R575.1 R658.4(I2) R698.2 U3.AA12(VCC#AA12) U3.AA22(VCC#AA22) U3.N21(VCC#N21) U3.N22(VCC#N22) U3.N24(VCC#N24) U3.P21(VCC#P21) U3.R20(VCC#R20) U3.R22(VCC#R22) U3.R24(VCC#R24) U3.T20(VCC#T20) U3.T22(VCC#T22) U3.U13(VCC#U13) U3.U19(VCC#U19) U3.U21(VCC#U21) U3.V17(VCC#V17) U3.V19(VCC#V19) U3.V21(VCC#V21) U3.W13(VCC#W13) U3.W15(VCC#W15) U3.W17(VCC#W17) U3.W20(VCC#W20) U3.Y14(VCC#Y14) U3.Y15(VCC#Y15) U3.Y19(VCC#Y19) VCCORE.1(TP)
VCC_DDR: C466.1 C467.1 C469.1 C470.1 C471.1 C472.1 C474.1 C475.1 C477.1 C479.1 C481.1 C482.1 C484.1 C486.1 C490.1 C492.1 C495.1 C498.1 C499.1 C500.1 C501.1 C502.1 C503.1 C504.1 C505.1 C506.1 C508.1 C511.1 C1221.1 C1222.1 C1223.1 C1224.1 C1225.1 C1226.1 C1227.1 C1228.1 C1229.1 C1230.1 C1231.1 C1232.1 C1233.1 C1235.1 C1238.1 C1240.1 C1242.1 C1245.1 C1246.1 C1247.1 C1248.1 C1249.1 C1250.1 C1251.1 C1252.1 C1253.1 C1254.1 C1256.1 FB29.2 J70.1 R291.1 R292.2 R293.2 R374.1 R633.1 R646.2 R647.2 U5.A4(VDD2_A4) U5.A9(VDD2_A9) U5.AA3(VDDQ_AA3) U5.AA5(VDDQ_AA5) U5.AA8(VDDQ_AA8) U5.AA10(VDDQ_AA10) U5.AB4(VDD2_AB4) U5.AB9(VDD2_AB9) U5.B3(VDDQ_B3) U5.B5(VDDQ_B5) U5.B8(VDDQ_B8) U5.B10(VDDQ_B10) U5.D1(VDDQ_D1) U5.D5(VDDQ_D5) U5.D8(VDDQ_D8) U5.D12(VDDQ_D12) U5.F3(VDDQ_F3) U5.F5(VDD2_F5) U5.F8(VDD2_F8) U5.F10(VDDQ_F10) U5.H1(VDD2_H1) U5.H5(VDD2_H5) U5.H8(VDD2_H8) U5.H12(VDD2_H12) U5.K1(VDD2_K1) U5.K3(VDD2_K3) U5.K10(VDD2_K10) U5.K12(VDD2_K12) U5.N1(VDD2_N1) U5.N3(VDD2_N3) U5.N10(VDD2_N10) U5.N12(VDD2_N12) U5.R1(VDD2_R1) U5.R5(VDD2_R5) U5.R8(VDD2_R8) U5.R12(VDD2_R12) U5.U3(VDDQ_U3) U5.U5(VDD2_U5) U5.U8(VDD2_U8) U5.U10(VDDQ_U10) U5.W1(VDDQ_W1) U5.W5(VDDQ_W5) U5.W8(VDDQ_W8) U5.W12(VDDQ_W12) U119.A4(VDD2_A4) U119.A9(VDD2_A9) U119.AA3(VDDQ_AA3) U119.AA5(VDDQ_AA5) U119.AA8(VDDQ_AA8) U119.AA10(VDDQ_AA10) U119.AB4(VDD2_AB4) U119.AB9(VDD2_AB9) U119.B3(VDDQ_B3) U119.B5(VDDQ_B5) U119.B8(VDDQ_B8) U119.B10(VDDQ_B10) U119.D1(VDDQ_D1) U119.D5(VDDQ_D5) U119.D8(VDDQ_D8) U119.D12(VDDQ_D12) U119.F3(VDDQ_F3) U119.F5(VDD2_F5) U119.F8(VDD2_F8) U119.F10(VDDQ_F10) U119.H1(VDD2_H1) U119.H5(VDD2_H5) U119.H8(VDD2_H8) U119.H12(VDD2_H12) U119.K1(VDD2_K1) U119.K3(VDD2_K3) U119.K10(VDD2_K10) U119.K12(VDD2_K12) U119.N1(VDD2_N1) U119.N3(VDD2_N3) U119.N10(VDD2_N10) U119.N12(VDD2_N12) U119.R1(VDD2_R1) U119.R5(VDD2_R5) U119.R8(VDD2_R8) U119.R12(VDD2_R12) U119.U3(VDDQ_U3) U119.U5(VDD2_U5) U119.U8(VDD2_U8) U119.U10(VDDQ_U10) U119.W1(VDDQ_W1) U119.W5(VDDQ_W5) U119.W8(VDDQ_W8) U119.W12(VDDQ_W12)
VCC_DDR_VDD1: C487.1 C489.1 C491.1 C493.1 C494.1 C496.1 C497.1 C510.1 C512.1 C1234.1 C1236.1 C1237.1 C1239.1 C1241.1 C1243.1 C1244.1 C1255.1 C1257.1 FB28.2 U5.F1(VDD1_F1) U5.F12(VDD1_F12) U5.G4(VDD1_G4) U5.G9(VDD1_G9) U5.T4(VDD1_T4) U5.T9(VDD1_T9) U5.U1(VDD1_U1) U5.U12(VDD1_U12) U119.F1(VDD1_F1) U119.F12(VDD1_F12) U119.G4(VDD1_G4) U119.G9(VDD1_G9) U119.T4(VDD1_T4) U119.T9(VDD1_T9) U119.U1(VDD1_U1) U119.U12(VDD1_U12)
VCCA_PLL4: C287.1 C289.1 J79.1 R540.1 U3.AA13(VCCA_PLL4) VCCAPLL4.1(TP)
VCCA_PLL4_IN: FB26.1 J79.2 R540.2
VCCA_PLL7: C292.1 C717.1 J80.1 R541.1 U3.Y16(VCCA_PLL7) VCCAPLL7.1(TP)
VCCA_PLL7_IN: FB27.1 J80.2 R541.2
VCCA_PLL10: C290.1 C293.1 J78.1 R539.1 U3.AA23(VCCA_PLL10) VCCAPLL10.1(TP)
VCCA_PLL10_IN: FB25.1 J78.2 R539.2
VCCA_PLLW: C288.1 C291.1 J77.1 R267.1 U3.P12(VCCA_PLL_W) VCCAPLLW.1(TP)
VCCA_PLLW_IN: FB22.1 J77.2 R267.2
VCCBAT_1V50: R714.1 U3.M16(VCC_BAT)
VCCIO0: C595.1 C596.1 C597.1 C598.1 J58.2 R139.2 U3.M12(VCCIO0#M12) U3.V3(VCCIO0#V3) U3.V7(VCCIO0#V7) VCCIO0.1(TP)
VCCIO1: C19.1 C20.1 C589.1 C590.1 J59.2 R143.1 U3.M7(VCCIO1#M7) U3.N8(VCCIO1#N8) U3.N11(VCCIO1#N11) VCCIO1.1(TP)
VCCIO1_IN: C23.2 C24.1 C25.1 FB6.1 J3.10 J59.1 R38.1 R39.1 R40.1 R41.1 R56.2 R57.2 R58.2 R59.2 R60.2 R61.2 R109.2 R143.2 R536.1 U4.8(VCC)
VCCIO2: C584.1 C586.1 C587.1 C588.1 J60.2 R140.2 U3.M10(VCCIO2#M10) U3.R2(VCCIO2#R2) U3.R4(VCCIO2#R4) VCCIO2.1(TP)
VCCIO2_IN: J60.1 R22.1 R24.2 R25.2 R26.1 R27.1 R140.1 R179.1 R657.1
VCCIO3: C37.1 C38.1 C39.1 C40.1 C531.1 C616.1 J65.2 R137.2 R712.2 U3.AB3(VCCIO3#AB3) U3.AB6(VCCIO3#AB6) U3.AB9(VCCIO3#AB9) U3.AC11(VCCIO3#AC11) VCCIO3.1(TP)
VCCIO3_IN: J65.1 JP60.2 JP69.2 JP70.2 R137.1
VCCIO4: C41.1 C42.1 C43.1 C44.1 C532.1 C615.1 J66.2 R142.2 R713.2 U3.AE8(VCCIO4#AE8) U3.AG4(VCCIO4#AG4) U3.AK3(VCCIO4#AK3) U3.AN2(VCCIO4#AN2) VCCIO4.1(TP)
VCCIO4_IN: J66.1 JP59.2 JP71.2 JP72.2 R142.1
VCCIO5: C55.1 C56.1 C57.1 C58.1 C533.1 C614.1 J67.2 R147.2 R711.2 U3.AD14(VCCIO5#AD14) U3.AH12(VCCIO5#AH12) U3.AJ9(VCCIO5#AJ9) U3.AL7(VCCIO5#AL7) VCCIO5.1(TP)
VCCIO5_IN: J67.1 JP58.2 JP73.2 JP74.2 R147.1
VCCIO6: C64.1 C65.1 C66.1 C579.1 C580.1 J71.2 R353.2 U3.AD16(VCCIO6#AD16) U3.AJ15(VCCIO6#AJ15) U3.AL12(VCCIO6#AL12) U3.AL15(VCCIO6#AL15) VCCIO6.1(TP)
VCCIO6_IN: C732.1 J71.1 JP31.2 JP32.2 JP33.2 JP34.2 JP35.2 JP36.2 R21.1 R30.1 R31.1 R32.1 R33.1 R34.1 R35.1 R36.1 R37.1 R47.1 R48.1 R353.1 R542.2 R543.2 U46.1(VCCA) U46.8(EN)
VCCIO7: C537.1 C538.1 C539.1 C543.1 C544.1 C618.1 J68.2 R378.2 R709.2 U3.AD18(VCCIO7#AD18) U3.AG19(VCCIO7#AG19) U3.AL19(VCCIO7#AL19) U3.AL22(VCCIO7#AL22) VCCIO7.1(TP)
VCCIO7_IN: J68.1 JP61.2 JP75.2 JP76.2 R378.1
VCCIO8: C534.1 C535.1 C536.1 C540.1 C541.1 C617.1 J69.2 R370.2 R710.2 U3.AC19(VCCIO8#AC19) U3.AF22(VCCIO8#AF22) U3.AJ24(VCCIO8#AJ24) U3.AM27(VCCIO8#AM27) VCCIO8.1(TP)
VCCIO8_IN: J69.1 JP62.2 JP77.2 JP78.2 R370.1
VCCIO10: C465.1 C468.1 C473.1 C476.1 C478.1 C480.1 C483.1 C485.1 C488.1 C507.1 C509.1 C542.1 C545.1 C546.1 C547.1 C548.1 C619.1 C631.1 J70.2 R290.2 R294.2 R374.2 R685.2 U3.AA25(VCCIO11#AA25) U3.AB22(VCCIO10#AB22) U3.AC28(VCCIO10#AC28) U3.AC31(VCCIO10#AC31) U3.AD24(VCCIO10#AD24) U3.AH27(VCCIO9#AH27) U3.AH31(VCCIO9#AH31) U3.AL31(VCCIO9#AL31) U3.AP33(VCCIO9#AP33) U3.V23(VCCIO11#V23) U3.W27(VCCIO11#W27) U3.W31(VCCIO11#W31) VCCIO9.1(TP) VCCIO10.1(TP) VCCIO11.1(TP)
VCCIO12: C31.1 C32.1 C33.1 C526.1 J72.2 R387.2 U3.M14(VCCIO12#M14) U3.N18(VCCIO12#N18) U3.P16(VCCIO12#P16) VCCIO12.1(TP)
VCCIO12_IN: J23.1 J57.1 J72.1 JP47.2 JP48.2 JP49.2 JP50.2 R82.1 R298.1 R387.1
VCCIO13: C527.1 C528.1 C529.1 C530.1 J63.2 R391.2 U3.M13(VCCIO13#M13) U3.T14(VCCIO13#T14) U3.T16(VCCIO13#T16) VCCIO13.1(TP)
VCCIO14: C591.1 C592.1 C593.1 C594.1 J64.2 R395.2 U3.N12(VCCIO14#N12) U3.U9(VCCIO14#U9) U3.U11(VCCIO14#U11) VCCIO14.1(TP)
VCCPLL_0V82: C719.1 FB22.2 FB25.2 FB26.2 FB27.2 R544.1 R547.2 R584.1 U44.1(OUT)
6_INCH_LONG_TRACE: U3.AH13(HPIO6_22A/DP1_DQ61) U3.AJ13(HPIO6_22B/DP1_DQ60) UNK6T.1
10_INCH_LONG_TRACE: U3.AM10(HPIO6_23A/DP1_DQ69) U3.AM11(HPIO6_23B/DP1_DQ68) UNK10T.1
12_MHZ: JP6.2 JP65.3
125_DIS: JP15.2 R109.1 U3.L7(WRIO1_4A/MDQ4) X3.1(STANDBY)
125_MHZ: R110.2 U3.N7(WRIO1_3B/PCLKRT1_0/MDS)
ASC_CLK: ASC_CLK.1 U45.G1(ASCCLK)
ASC_RDAT: RDAT.1 U45.E3(RDAT)
ASC_WDAT: U45.H1(WDAT) WDAT.1
ASC_WRCLK: U45.G2(WRCLK) WRCLK.1
B6_SCL: JP64.3 R542.1 U3.AH16(HPIO6_10A/PCLKT6_0/PCLKRT6_0/DP)
B6_SDA: JP64.1 R543.1 U3.AG16(HPIO6_10B/PCLKC6_0/PCLKRC6_0)
CFGMODE: SW7.2(COM_1) SW7.5(COM_2) U3.P1(CFGMODE)
CSSPIN: J3.8 JP51.1 U3.P7(WRIO1_3A/MCSN)
DIP_SW1: R30.2 SW3.1(A1) U3.AA16(HPIO6_0A/DP1_DQ43)
DIP_SW2: R31.2 SW3.2(A2) U3.AA17(HPIO6_0B/DP1_DQ42)
DIP_SW3: R32.2 SW3.3(A3) U3.AL16(HPIO6_1A/DP1_DQ51)
DIP_SW4: R33.2 SW3.4(A4) U3.AM16(HPIO6_1B/DP1_DQ50)
DIP_SW5: R34.2 SW3.5(A5) U3.AB16(HPIO6_2A/DP1_DQ47)
DIP_SW6: R35.2 SW3.6(A6) U3.AB17(HPIO6_2B/DP1_DQ46)
DIP_SW7: R36.2 SW3.7(A7) U3.AP16(HPIO6_3A/DP1_DQ55)
DIP_SW8: R37.2 SW3.8(A8) U3.AN16(HPIO6_3B/DP1_DQ54)
DM: D3.3(NC3) D3.4(D-) J2.2(D-) U1.7(DM)
DONE: DONE.1(TP) J3.4 R26.2 R28.2 U3.U4(DONE)
DP: D3.2(NC2) D3.5(D+) J2.3(D+) U1.8(DP)
DQ0_MOSI: J3.5 R46.1 U3.L12(WRIO1_0A/MDQ0)
DQ1_MISO: J3.7 R43.1 U3.L11(WRIO1_0B/MDQ1)
DQ2: J3.11 R45.2 U3.L10(WRIO1_2A/MDQ2)
DQ3: J3.9 R44.1 U3.L9(WRIO1_2B/MDQ3)
EN_CORE_0V82: C1663.1 R702.2 R703.2 R704.1 R708.1 U120.6(EN)
EPS1_AN13_P: TP_AN13.1(TP) U3.AN13(HPIO6_11A/PCLKT6_1/PCLKRT6_1/DP)
EPS1_AP13_N: TP_AP13.1(TP) U3.AP13(HPIO6_11B/PCLKC6_1/PCLKRC6_1)
EPS2_AJ16: TP_AJ16.1(TP) U3.AJ16(HPIO6_12A/VREF6/DP1_VREF6)
EPS2_AK16: TP_AK16.1(TP) U3.AK16(EXT_RES6/DP1_EXT_RES6)
EPS3_AL13_P: TP_AL13.1(TP) U3.AL13(HPIO6_13A/PLLT6_IN)
EPS3_AM13_N: TP_AM13.1(TP) U3.AM13(HPIO6_13B/PLLC6_IN)
EPS4_AG15_P: TP_AG15.1(TP) U3.AG15(HPIO6_14A/DP1_DQ59)
EPS4_AH15_N: TP_AH15.1(TP) U3.AH15(HPIO6_14B/DP1_DQ58)
EPS5_AK12_N: TP_AK12.1(TP) U3.AK12(HPIO6_15B/DP1_DQ66)
EPS5_AK13_P: TP_AK13.1(TP) U3.AK13(HPIO6_15A/DP1_DQ67)
EPS6_AF15_P: TP_AF15.1(TP) U3.AF15(HPIO6_16A/DP1_DQ63)
EPS6_AF16_N: TP_AF16.1(TP) U3.AF16(HPIO6_16B/DP1_DQ62)
EPS7_AN12_N: TP_AN12.1(TP) U3.AN12(HPIO6_17B/DP1_DQ70)
EPS7_AP12_P: TP_AP12.1(TP) U3.AP12(HPIO6_17A/DP1_DQ71)
EPS8_AG14_N: TP_AG14.1(TP) U3.AG14(HPIO6_18B/DP1_DQSN7)
EPS8_AH14_P: TP_AH14.1(TP) U3.AH14(HPIO6_18A/DP1_DQS7)
EPS9_AP10_P: TP_AP10.1(TP) U3.AP10(HPIO6_19A/DP1_DQS8)
EPS9_AP11_N: TP_AP11.1(TP) U3.AP11(HPIO6_19B/DP1_DQSN8)
EPS10_AK14_P: TP_AK14.1(TP) U3.AK14(HPIO6_20A/DP1_DQ57)
EPS10_AK15_N: TP_AK15.1(TP) U3.AK15(HPIO6_20B/DP1_DQ56)
F_DDR_100MHZ_N: R491.2 R538.1 U3.AD31(HPIO10_13B/PLLC10_IN/DP2_PLLC10)
F_DDR_100MHZ_P: R490.1 R537.1 U3.AD32(HPIO10_13A/PLLT10_IN/DP2_PLLT10)
F_K_DIG1: R343.1 U3.W9(WRIO14_4A)
F_K_DIG2: R339.1 U3.V9(WRIO14_4B)
F_K_DIG3: R341.1 U3.R10(WRIO14_9B)
FLASH_CS: J3.2 JP51.2 R38.2 U4.1(CS#)
FMC1_CLK0_M2C_N: J48.H5(CLK0_M2C_N) U3.Y6(HPIO3_25B/PCLKRC3_3)
FMC1_CLK0_M2C_P: J48.H4(CLK0_M2C_P) U3.Y7(HPIO3_25A/PCLKRT3_3/DP0_DM8)
FMC1_CLK1_M2C_N: J48.G3(CLK1_M2C_N) U3.AE6(HPIO4_10B/PCLKC4_0/PCLKRC4_0/DP)
FMC1_CLK1_M2C_P: J48.G2(CLK1_M2C_P) U3.AF6(HPIO4_10A/PCLKT4_0/PCLKRT4_0/DP)
FMC1_CLK2_M2C_N: J48.K5(CLK2_M2C_N) U3.AJ6(HPIO5_25B/PCLKRC5_3/DP0_RAS_N)
FMC1_CLK2_M2C_P: J48.K4(CLK2_M2C_P) U3.AJ5(HPIO5_25A/PCLKRT5_3/DP0_BA0)
FMC1_CLK3_M2C_N: J48.J3(CLK3_M2C_N) U3.AE1(HPIO4_24B/PCLKRC4_2/DP0_ALERT_N)
FMC1_CLK3_M2C_P: J48.J2(CLK3_M2C_P) U3.AF1(HPIO4_24A/PCLKRT4_2/DP0_DM0)
FMC1_GA0: J48.C34(GA0) R249.1 R251.2
FMC1_GA1: J48.D35(GA1) R250.1 R252.2
FMC1_HA00_CLK_N: J48.F5(HA00_N_CC) U3.AJ11(HPIO5_10B/PCLKC5_0/PCLKRC5_0)
FMC1_HA00_CLK_P: J48.F4(HA00_P_CC) U3.AJ12(HPIO5_10A/PCLKT5_0/PCLKRT5_0/DP)
FMC1_HA01_CLK_N: J48.E3(HA01_N_CC) U3.AE12(HPIO5_24B/PCLKRC5_2/DP0_CAS_N)
FMC1_HA01_CLK_P: J48.E2(HA01_P_CC) U3.AF12(HPIO5_24A/PCLKRT5_2/DP0_DM3)
FMC1_HA02_N: J48.K8(HA02_N) U3.AF14(HPIO5_6B/DP0_DQ39)
FMC1_HA02_P: J48.K7(HA02_P) U3.AE14(HPIO5_6A/DP0_DQ38)
FMC1_HA03_N: J48.J7(HA03_N) U3.AC14(HPIO5_4B/DP0_DQSN4)
FMC1_HA03_P: J48.J6(HA03_P) U3.AC15(HPIO5_4A/DP0_DQS4)
FMC1_HA04_N: J48.F8(HA04_N) U3.AA14(HPIO5_0B/DP0_DQ37)
FMC1_HA04_P: J48.F7(HA04_P) U3.AA15(HPIO5_0A/DP0_DQ36)
FMC1_HA05_N: J48.E7(HA05_N) U3.AB15(HPIO5_2B/DP0_DQ33)
FMC1_HA05_P: J48.E6(HA05_P) U3.AB14(HPIO5_2A/DP0_DQ32)
FMC1_HA06_N: J48.K11(HA06_N) U3.AJ7(HPIO5_21B/DP0_WE_N)
FMC1_HA06_P: J48.K10(HA06_P) U3.AK7(HPIO5_21A/DP0_MA14)
FMC1_HA07_N: J48.J10(HA07_N) U3.AJ10(HPIO5_16B/DP0_DQ25)
FMC1_HA07_P: J48.J9(HA07_P) U3.AH10(HPIO5_16A/DP0_DQ24)
FMC1_HA08_N: J48.F11(HA08_N) U3.AG11(HPIO5_20B/DP0_DQ31)
FMC1_HA08_P: J48.F10(HA08_P) U3.AG10(HPIO5_20A/DP0_DQ30)
FMC1_HA09_N: J48.E10(HA09_N) U3.AG13(HPIO5_8B/DP0_DQ35)
FMC1_HA09_P: J48.E9(HA09_P) U3.AG12(HPIO5_8A/DP0_DQ34)
FMC1_HA10_N: J48.K14(HA10_N) U3.AL9(HPIO5_3B/DP0_DQ17)
FMC1_HA10_P: J48.K13(HA10_P) U3.AL8(HPIO5_3A/DP0_DQ16)
FMC1_HA11_N: J48.J13(HA11_N) U3.AL6(HPIO5_19B/DP0_MA15)
FMC1_HA11_P: J48.J12(HA11_P) U3.AL5(HPIO5_19A/DP0_MA16)
FMC1_HA12_N: J48.F14(HA12_N) U3.AH8(HPIO5_22B/DP0_DQ27)
FMC1_HA12_P: J48.F13(HA12_P) U3.AH7(HPIO5_22A/DP0_DQ26)
FMC1_HA13_N: J48.E13(HA13_N) U3.AG9(HPIO5_18B/DP0_DQSN3)
FMC1_HA13_P: J48.E12(HA13_P) U3.AH9(HPIO5_18A/DP0_DQS3)
FMC1_HA14_N: J48.J16(HA14_N) U3.AP8(HPIO5_9B/DP0_DQ19)
FMC1_HA14_P: J48.J15(HA14_P) U3.AP9(HPIO5_9A/DP0_DQ18)
FMC1_HA15_N: J48.F17(HA15_N) U3.AK6(HPIO5_23B/DP0_BA1)
FMC1_HA15_P: J48.F16(HA15_P) U3.AK5(HPIO5_23A/DP0_BA2)
FMC1_HA16_N: J48.E16(HA16_N) U3.AK11(HPIO5_14B/DP0_DQ29)
FMC1_HA16_P: J48.E15(HA16_P) U3.AK10(HPIO5_14A/DP0_DQ28)
FMC1_HA17_CLK_N: J48.K17(HA17_N_CC) U3.AP7(HPIO5_11B/PCLKC5_1/PCLKRC5_1)
FMC1_HA17_CLK_P: J48.K16(HA17_P_CC) U3.AN7(HPIO5_11A/PCLKT5_1/PCLKRT5_1/DP)
FMC1_HA18_N: J48.J19(HA18_N) U3.AM9(HPIO5_5B/DP0_DQSN2)
FMC1_HA18_P: J48.J18(HA18_P) U3.AM8(HPIO5_5A/DP0_DQS2)
FMC1_HA19_N: J48.F20(HA19_N) U3.AK8(HPIO5_1B/DP0_DQ21)
FMC1_HA19_P: J48.F19(HA19_P) U3.AK9(HPIO5_1A/DP0_DQ20)
FMC1_HA20_N: J48.E19(HA20_N) U3.AM5(HPIO5_17B/DP0_MCLKC2)
FMC1_HA20_P: J48.E18(HA20_P) U3.AM6(HPIO5_17A/DP0_MCLKT2)
FMC1_HA21_N: J48.K20(HA21_N) U3.AN5(HPIO5_15B/DP0_MCLKC3)
FMC1_HA21_P: J48.K19(HA21_P) U3.AN6(HPIO5_15A/DP0_MCLKT3)
FMC1_HA22_N: J48.J22(HA22_N) U3.AP6(HPIO5_13B/PLLC5_IN)
FMC1_HA22_P: J48.J21(HA22_P) U3.AP5(HPIO5_13A/PLLT5_IN)
FMC1_HA23_N: J48.K23(HA23_N) U3.AN8(HPIO5_7B/DP0_DQ23)
FMC1_HA23_P: J48.K22(HA23_P) U3.AN9(HPIO5_7A/DP0_DQ22)
FMC1_HB00_N_CC: J48.K26(HB00_N_CC) U3.AC1(HPIO3_11B/PCLKC3_1/PCLKRC3_1)
FMC1_HB00_P_CC: J48.K25(HB00_P_CC) U3.AB1(HPIO3_11A/PCLKT3_1/PCLKRT3_1/DP)
FMC1_HB01_N: J48.J25(HB01_N) U3.AD10(HPIO3_6B/DP0_DQ40)
FMC1_HB01_P: J48.J24(HB01_P) U3.AD9(HPIO3_6A/DP0_DQ41)
FMC1_HB02_N: J48.F23(HB02_N) U3.AD5(HPIO3_1B/DP0_DQ50)
FMC1_HB02_P: J48.F22(HB02_P) U3.AD6(HPIO3_1A/DP0_DQ51)
FMC1_HB03_N: J48.E22(HB03_N) U3.AC5(HPIO3_5B/DP0_DQSN6)
FMC1_HB03_P: J48.E21(HB03_P) U3.AC4(HPIO3_5A/DP0_DQS6)
FMC1_HB04_N: J48.F26(HB04_N) U3.AC10(HPIO3_20B/DP0_DQ56)
FMC1_HB04_P: J48.F25(HB04_P) U3.AB10(HPIO3_20A/DP0_DQ57)
FMC1_HB05_N: J48.E25(HB05_N) U3.AD8(HPIO3_8B/DP0_DQ44)
FMC1_HB05_P: J48.E24(HB05_P) U3.AD7(HPIO3_8A/DP0_DQ45)
FMC1_HB06_N_CC: J48.K29(HB06_N_CC) U3.AM2(HPIO4_13B/PLLC4_IN/DP0_PLLC4_IN)
FMC1_HB06_P_CC: J48.K28(HB06_P_CC) U3.AL2(HPIO4_13A/PLLT4_IN/DP0_PLLT4_IN)
FMC1_HB07_N: J48.J28(HB07_N) U3.AD11(HPIO3_4B/DP0_DQSN5)
FMC1_HB07_P: J48.J27(HB07_P) U3.AD12(HPIO3_4A/DP0_DQS5)
FMC1_HB08_N: J48.F29(HB08_N) U3.AF7(HPIO4_8B/DP0_MA6)
FMC1_HB08_P: J48.F28(HB08_P) U3.AE7(HPIO4_8A/DP0_MA5)
FMC1_HB09_N: J48.E28(HB09_N) U3.AF5(HPIO4_14B/DP0_DQ02)
FMC1_HB09_P: J48.E27(HB09_P) U3.AE5(HPIO4_14A/DP0_DQ03)
FMC1_HB10_N: J48.K32(HB10_N) U3.AN3(HPIO4_9B/DP0_MA11)
FMC1_HB10_P: J48.K31(HB10_P) U3.AM3(HPIO4_9A/DP0_MA10)
FMC1_HB11_N: J48.J31(HB11_N) U3.AK4(HPIO4_3B/DP0_ODT1)
FMC1_HB11_P: J48.J30(HB11_P) U3.AJ4(HPIO4_3A/DP0_CKE1)
FMC1_HB12_N: J48.F32(HB12_N) U3.AH3(HPIO4_21B/DP0_DQ08)
FMC1_HB12_P: J48.F31(HB12_P) U3.AH4(HPIO4_21A/DP0_DQ09)
FMC1_LA00_CLK_N: J48.G7(LA00_N_CC) U3.AA7(HPIO3_24B/PCLKRC3_2)
FMC1_LA00_CLK_P: J48.G6(LA00_P_CC) U3.AB7(HPIO3_24A/PCLKRT3_2/DP0_DM7)
FMC1_LA01_CLK_N: J48.D9(LA01_N_CC) U3.AC9(HPIO3_10B/PCLKC3_0/PCLKRC3_0)
FMC1_LA01_CLK_P: J48.D8(LA01_P_CC) U3.AC8(HPIO3_10A/PCLKT3_0/PCLKRT3_0/DP)
FMC1_LA02_N: J48.H8(LA02_N) U3.AB12(HPIO3_0B/DP0_DQ42)
FMC1_LA02_P: J48.H7(LA02_P) U3.AB13(HPIO3_0A/DP0_DQ43)
FMC1_LA03_N: J48.G10(LA03_N) U3.Y10(HPIO3_14B/DP0_DQ58)
FMC1_LA03_P: J48.G9(LA03_P) U3.Y11(HPIO3_14A/DP0_DQ59)
FMC1_LA04_N: J48.H11(LA04_N) U3.AC12(HPIO3_2B/DP0_DQ46)
FMC1_LA04_P: J48.H10(LA04_P) U3.AC13(HPIO3_2A/DP0_DQ47)
FMC1_LA05_N: J48.D12(LA05_N) U3.AA9(HPIO3_22B/DP0_DQ60)
FMC1_LA05_P: J48.D11(LA05_P) U3.AA8(HPIO3_22A/DP0_DQ61)
FMC1_LA06_N: J48.C11(LA06_N) U3.Y9(HPIO3_16B/DP0_DQ62)
FMC1_LA06_P: J48.C10(LA06_P) U3.Y8(HPIO3_16A/DP0_DQ63)
FMC1_LA07_N: J48.H14(LA07_N) U3.AA1(HPIO3_13B/PLLC3_IN)
FMC1_LA07_P: J48.H13(LA07_P) U3.Y1(HPIO3_13A/PLLT3_IN)
FMC1_LA08_N: J48.G13(LA08_N) U3.AB5(HPIO3_19B/DP0_DQSN8)
FMC1_LA08_P: J48.G12(LA08_P) U3.AB4(HPIO3_19A/DP0_DQS8)
FMC1_LA09_N: J48.D15(LA09_N) U3.Y2(HPIO3_15B/DP0_DQ66)
FMC1_LA09_P: J48.D14(LA09_P) U3.AA2(HPIO3_15A/DP0_DQ67)
FMC1_LA10_N: J48.C15(LA10_N) U3.AA5(HPIO3_23B/DP0_DQ68)
FMC1_LA10_P: J48.C14(LA10_P) U3.Y5(HPIO3_23A/DP0_DQ69)
FMC1_LA11_N: J48.H17(LA11_N) U3.AD4(HPIO3_3B/DP0_DQ54)
FMC1_LA11_P: J48.H16(LA11_P) U3.AD3(HPIO3_3A/DP0_DQ55)
FMC1_LA12_N: J48.G16(LA12_N) U3.Y3(HPIO3_17B/DP0_DQ70)
FMC1_LA12_P: J48.G15(LA12_P) U3.AA3(HPIO3_17A/DP0_DQ71)
FMC1_LA13_N: J48.D18(LA13_N) U3.Y4(HPIO3_21B/DP0_DQ64)
FMC1_LA13_P: J48.D17(LA13_P) U3.AA4(HPIO3_21A/DP0_DQ65)
FMC1_LA14_N: J48.C19(LA14_N) U3.AC2(HPIO3_7B/DP0_DQ48)
FMC1_LA14_P: J48.C18(LA14_P) U3.AC3(HPIO3_7A/DP0_DQ49)
FMC1_LA15_N: J48.H20(LA15_N) U3.AC6(HPIO3_18B/DP0_DQSN7)
FMC1_LA15_P: J48.H19(LA15_P) U3.AC7(HPIO3_18A/DP0_DQS7)
FMC1_LA16_N: J48.G19(LA16_N) U3.AD1(HPIO3_9B/DP0_DQ52)
FMC1_LA16_P: J48.G18(LA16_P) U3.AD2(HPIO3_9A/DP0_DQ53)
FMC1_LA17_CLK_N: J48.D21(LA17_N_CC) U3.AP3(HPIO4_11B/PCLKC4_1/PCLKRC4_1/DP)
FMC1_LA17_CLK_P: J48.D20(LA17_P_CC) U3.AP2(HPIO4_11A/PCLKT4_1/PCLKRT4_1/DP)
FMC1_LA18_CLK_N: J48.C23(LA18_N_CC) U3.AJ1(HPIO4_25B/PCLKRC4_3/DP0_RST_N)
FMC1_LA18_CLK_P: J48.C22(LA18_P_CC) U3.AH1(HPIO4_25A/PCLKRT4_3/DP0_DM1)
FMC1_LA19_N: J48.H23(LA19_N) U3.AF4(HPIO4_16B/DP0_DQ06)
FMC1_LA19_P: J48.H22(LA19_P) U3.AE4(HPIO4_16A/DP0_DQ07)
FMC1_LA20_N: J48.G22(LA20_N) U3.AF2(HPIO4_20B/DP0_DQ00)
FMC1_LA20_P: J48.G21(LA20_P) U3.AE2(HPIO4_20A/DP0_DQ01)
FMC1_LA21_N: J48.H26(LA21_N) U3.AK2(HPIO4_19B/DP0_DQSN1)
FMC1_LA21_P: J48.H25(LA21_P) U3.AJ2(HPIO4_19A/DP0_DQS1)
FMC1_LA22_N: J48.G25(LA22_N) U3.AG2(HPIO4_22B/DP0_DQ04)
FMC1_LA22_P: J48.G24(LA22_P) U3.AG1(HPIO4_22A/DP0_DQ05)
FMC1_LA23_N: J48.D24(LA23_N) U3.AE3(HPIO4_18B/DP0_DQSN0)
FMC1_LA23_P: J48.D23(LA23_P) U3.AF3(HPIO4_18A/DP0_DQS0)
FMC1_LA24_N: J48.H29(LA24_N) U3.AJ3(HPIO4_23B/DP0_DQ12)
FMC1_LA24_P: J48.H28(LA24_P) U3.AH2(HPIO4_23A/DP0_DQ13)
FMC1_LA25_N: J48.G28(LA25_N) U3.AK1(HPIO4_17B/DP0_DQ14)
FMC1_LA25_P: J48.G27(LA25_P) U3.AL1(HPIO4_17A/DP0_DQ15)
FMC1_LA26_N: J48.D27(LA26_N) U3.AF11(HPIO4_0B/DP0_MCLKC0)
FMC1_LA26_P: J48.D26(LA26_P) U3.AE11(HPIO4_0A/DP0_MCLKT0)
FMC1_LA27_N: J48.C27(LA27_N) U3.AE10(HPIO4_2B/DP0_MA0)
FMC1_LA27_P: J48.C26(LA27_P) U3.AF10(HPIO4_2A/DP0_CKE0)
FMC1_LA28_N: J48.H32(LA28_N) U3.AH5(HPIO4_1B/DP0_MCLKC1)
FMC1_LA28_P: J48.H31(LA28_P) U3.AH6(HPIO4_1A/DP0_MCLKT1)
FMC1_LA29_N: J48.G31(LA29_N) U3.AG8(HPIO4_6B/DP0_MA4)
FMC1_LA29_P: J48.G30(LA29_P) U3.AG7(HPIO4_6A/DP0_MA3)
FMC1_LA30_N: J48.H35(LA30_N) U3.AM1(HPIO4_15B/DP0_DQ10)
FMC1_LA30_P: J48.H34(LA30_P) U3.AN1(HPIO4_15A/DP0_DQ11)
FMC1_LA31_N: J48.G34(LA31_N) U3.AE9(HPIO4_4B/DP0_MA2)
FMC1_LA31_P: J48.G33(LA31_P) U3.AF9(HPIO4_4A/DP0_MA1)
FMC1_LA32_N: J48.H38(LA32_N) U3.AP4(HPIO4_7B/DP0_MA9)
FMC1_LA32_P: J48.H37(LA32_P) U3.AN4(HPIO4_7A/DP0_CS_N0)
FMC1_LA33_N: J48.G37(LA33_N) U3.AL4(HPIO4_5B/DP0_CS_N1)
FMC1_LA33_P: J48.G36(LA33_P) U3.AM4(HPIO4_5A/DP0_ODT0)
FMC1_PG_C2M: J10.4 J48.D1(PG_C2M) R83.1 U3.V4(WRIO0_2A)
FMC1_PG_M2C: J10.5 J48.F1(PG_M2C) R84.1 U3.W4(WRIO0_2B)
FMC1_PRSNT_M2C_L: J10.8 J48.H2(PRSNT_M2C_L) R217.1 U3.U7(WRIO0_3A)
FMC1_RES0: R216.2 U3.W5(WRIO0_0A)
FMC1_RES1: R215.2 U3.V5(WRIO0_0B)
FMC1_SCL: J10.10 J48.C30(SCL) R90.1 U3.T8(WRIO0_1B/PCLKT0_1/PCLKRT0_1)
FMC1_SDA: J10.14 J48.C31(SDA) R91.1 U3.U8(WRIO0_1A)
FMC1_TCK: J10.3 J48.D29(TCK) R55.1 R92.1
FMC1_TDI: J10.7 J48.D30(TDI) R85.1 U3.W1(WRIO0_4A)
FMC1_TDO: J10.9 J48.D31(TDO) R86.1 U3.V1(WRIO0_4B)
FMC1_TMS: J10.13 J48.D33(TMS) R87.1 U3.W7(WRIO0_5A)
FMC1_TRST_L: J10.6 J48.D34(TRST_L)
FMC1_VREFA: J48.H1(VREF_A_M2C) JP38.2 JP88.3 JP89.3
FMC1_VREFB: J48.K1(VREF_B_M2C) JP88.1 JP89.1
FMC2_CLK0_M2C_N: J54.H5(CLK0_M2C_N) U3.AH20(HPIO7_10B/PCLKC7_0/PCLKRC7_0/DP)
FMC2_CLK0_M2C_P: J54.H4(CLK0_M2C_P) U3.AG20(HPIO7_10A/PCLKT7_0/PCLKRT7_0/DP)
FMC2_CLK1_M2C_N: J54.G3(CLK1_M2C_N) U3.AE23(HPIO8_10B/PCLKC8_0/PCLKRC8_0)
FMC2_CLK1_M2C_P: J54.G2(CLK1_M2C_P) U3.AE22(HPIO8_10A/PCLKT8_0/PCLKRT8_0/DP)
FMC2_CLK2_M2C_N: J54.K5(CLK2_M2C_N) U3.AN21(HPIO7_13B/PLLC7_IN/DP1_PLLC7_IN)
FMC2_CLK2_M2C_P: J54.K4(CLK2_M2C_P) U3.AP21(HPIO7_13A/PLLT7_IN/DP1_PLLT7_IN)
FMC2_CLK3_M2C_N: J54.J3(CLK3_M2C_N) U3.AN29(HPIO8_13B/PLLC8_IN)
FMC2_CLK3_M2C_P: J54.J2(CLK3_M2C_P) U3.AP29(HPIO8_13A/PLLT8_IN)
FMC2_GA0: J54.C34(GA0) R323.1 R325.2
FMC2_GA1: J54.D35(GA1) R324.1 R326.2
FMC2_HA00_CLK_N: J54.F5(HA00_N_CC) U3.AL24(HPIO8_25B/PCLKRC8_3/DP1_RAS_N)
FMC2_HA00_CLK_P: J54.F4(HA00_P_CC) U3.AM24(HPIO8_25A/PCLKRT8_3/DP1_BA0)
FMC2_HA01_CLK_N: J54.E3(HA01_N_CC) U3.AN17(HPIO7_25B/PCLKRC7_3/DP1_RST_N)
FMC2_HA01_CLK_P: J54.E2(HA01_P_CC) U3.AP17(HPIO7_25A/PCLKRT7_3/DP1_DM1)
FMC2_HA02_N: J54.K8(HA02_N) U3.AN26(HPIO8_19B/DP1_MA15)
FMC2_HA02_P: J54.K7(HA02_P) U3.AP26(HPIO8_19A/DP1_MA16)
FMC2_HA03_N: J54.J7(HA03_N) U3.AP24(HPIO8_23B/DP1_BA1)
FMC2_HA03_P: J54.J6(HA03_P) U3.AN24(HPIO8_23A/DP1_BA2)
FMC2_HA04_N: J54.F8(HA04_N) U3.AP25(HPIO8_21B/DP1_WE_N)
FMC2_HA04_P: J54.F7(HA04_P) U3.AN25(HPIO8_21A/DP1_MA14)
FMC2_HA05_N: J54.E7(HA05_N) U3.AM25(HPIO8_17B/DP1_MCLKC2)
FMC2_HA05_P: J54.E6(HA05_P) U3.AM26(HPIO8_17A/DP1_MCLKT2)
FMC2_HA06_N: J54.K11(HA06_N) U3.AK26(HPIO8_3B/DP1_DQ17)
FMC2_HA06_P: J54.K10(HA06_P) U3.AL26(HPIO8_3A/DP1_DQ16)
FMC2_HA07_N: J54.J10(HA07_N) U3.AM20(HPIO7_7B/DP1_MA9)
FMC2_HA07_P: J54.J9(HA07_P) U3.AL20(HPIO7_7A/DP1_CS_N0)
FMC2_HA08_N: J54.F11(HA08_N) U3.AG18(HPIO7_16B/DP1_DQ06)
FMC2_HA08_P: J54.F10(HA08_P) U3.AH18(HPIO7_16A/DP1_DQ07)
FMC2_HA09_N: J54.E10(HA09_N) U3.AE17(HPIO7_4B/DP1_MA2)
FMC2_HA09_P: J54.E9(HA09_P) U3.AD17(HPIO7_4A/DP1_MA1)
FMC2_HA10_N: J54.K14(HA10_N) U3.AP23(HPIO7_9B/DP1_MA11)
FMC2_HA10_P: J54.K13(HA10_P) U3.AN23(HPIO7_9A/DP1_MA10)
FMC2_HA11_N: J54.J13(HA11_N) U3.AP18(HPIO7_21B/DP1_DQ08)
FMC2_HA11_P: J54.J12(HA11_P) U3.AN18(HPIO7_21A/DP1_DQ09)
FMC2_LA00_CLK_N: J54.G7(LA00_N_CC) U3.AK18(HPIO7_24B/PCLKRC7_2/DP1_ALERT_N)
FMC2_LA00_CLK_P: J54.G6(LA00_P_CC) U3.AJ18(HPIO7_24A/PCLKRT7_2/DP1_DM0)
FMC2_LA01_CLK_N: J54.D9(LA01_N_CC) U3.AN22(HPIO7_11B/PCLKC7_1/PCLKRC7_1/DP)
FMC2_LA01_CLK_P: J54.D8(LA01_P_CC) U3.AP22(HPIO7_11A/PCLKT7_1/PCLKRT7_1/DP)
FMC2_LA02_N: J54.H8(LA02_N) U3.AJ19(HPIO7_22B/DP1_DQ04)
FMC2_LA02_P: J54.H7(LA02_P) U3.AK19(HPIO7_22A/DP1_DQ05)
FMC2_LA03_N: J54.G10(LA03_N) U3.Y18(HPIO7_2B/DP1_MA0)
FMC2_LA03_P: J54.G9(LA03_P) U3.Y17(HPIO7_2A/DP1_CKE0)
FMC2_LA04_N: J54.H11(LA04_N) U3.AL17(HPIO7_23B/DP1_DQ12)
FMC2_LA04_P: J54.H10(LA04_P) U3.AM17(HPIO7_23A/DP1_DQ13)
FMC2_LA05_N: J54.D12(LA05_N) U3.AE19(HPIO7_6B/DP1_MA4)
FMC2_LA05_P: J54.D11(LA05_P) U3.AE18(HPIO7_6A/DP1_MA3)
FMC2_LA06_N: J54.C11(LA06_N) U3.AA18(HPIO7_0B/DP1_MCLKC0)
FMC2_LA06_P: J54.C10(LA06_P) U3.AB18(HPIO7_0A/DP1_MCLKT0)
FMC2_LA07_N: J54.H14(LA07_N) U3.AJ20(HPIO7_20B/DP1_DQ00)
FMC2_LA07_P: J54.H13(LA07_P) U3.AK20(HPIO7_20A/DP1_DQ01)
FMC2_LA08_N: J54.G13(LA08_N) U3.AL18(HPIO7_19B/DP1_DQSN1)
FMC2_LA08_P: J54.G12(LA08_P) U3.AM18(HPIO7_19A/DP1_DQS1)
FMC2_LA09_N: J54.D15(LA09_N) U3.AF20(HPIO7_8B/DP1_MA6)
FMC2_LA09_P: J54.D14(LA09_P) U3.AF19(HPIO7_8A/DP1_MA5)
FMC2_LA10_N: J54.C15(LA10_N) U3.AP20(HPIO7_15B/DP1_DQ10)
FMC2_LA10_P: J54.C14(LA10_P) U3.AN20(HPIO7_15A/DP1_DQ11)
FMC2_LA11_N: J54.H17(LA11_N) U3.AP19(HPIO7_17B/DP1_DQ14)
FMC2_LA11_P: J54.H16(LA11_P) U3.AN19(HPIO7_17A/DP1_DQ15)
FMC2_LA12_N: J54.G16(LA12_N) U3.AL21(HPIO7_5B/DP1_CS_N1)
FMC2_LA12_P: J54.G15(LA12_P) U3.AM21(HPIO7_5A/DP1_ODT0)
FMC2_LA13_N: J54.D18(LA13_N) U3.AK22(HPIO7_1B/DP1_MCLKC1)
FMC2_LA13_P: J54.D17(LA13_P) U3.AK21(HPIO7_1A/DP1_MCLKT1)
FMC2_LA14_N: J54.C19(LA14_N) U3.AL23(HPIO7_3B/DP1_ODT1)
FMC2_LA14_P: J54.C18(LA14_P) U3.AM23(HPIO7_3A/DP1_CKE1)
FMC2_LA15_N: J54.H20(LA15_N) U3.AH22(HPIO7_14B/DP1_DQ02)
FMC2_LA15_P: J54.H19(LA15_P) U3.AH21(HPIO7_14A/DP1_DQ03)
FMC2_LA16_N: J54.G19(LA16_N) U3.AJ21(HPIO7_18B/DP1_DQSN0)
FMC2_LA16_P: J54.G18(LA16_P) U3.AJ22(HPIO7_18A/DP1_DQS0)
FMC2_LA17_CLK_N: J54.D21(LA17_N_CC) U3.AM28(HPIO8_11B/PCLKC8_1/PCLKRC8_1)
FMC2_LA17_CLK_P: J54.D20(LA17_P_CC) U3.AN28(HPIO8_11A/PCLKT8_1/PCLKRT8_1/DP)
FMC2_LA18_CLK_N: J54.C23(LA18_N_CC) U3.AK23(HPIO8_24B/PCLKRC8_2/DP1_CAS_N)
FMC2_LA18_CLK_P: J54.C22(LA18_P_CC) U3.AK24(HPIO8_24A/PCLKRT8_2/DP1_DM3)
FMC2_LA19_N: J54.H23(LA19_N) U3.AD20(HPIO8_6B/DP1_DQ39)
FMC2_LA19_P: J54.H22(LA19_P) U3.AD19(HPIO8_6A/DP1_DQ38)
FMC2_LA20_N: J54.G22(LA20_N) U3.AE21(HPIO8_8B/DP1_DQ35)
FMC2_LA20_P: J54.G21(LA20_P) U3.AE20(HPIO8_8A/DP1_DQ34)
FMC2_LA21_N: J54.H26(LA21_N) U3.AG21(HPIO8_18B/DP1_DQSN3)
FMC2_LA21_P: J54.H25(LA21_P) U3.AF21(HPIO8_18A/DP1_DQS3)
FMC2_LA22_N: J54.G25(LA22_N) U3.AB20(HPIO8_0B/DP1_DQ36)
FMC2_LA22_P: J54.G24(LA22_P) U3.AC20(HPIO8_0A/DP1_DQ37)
FMC2_LA23_N: J54.D24(LA23_N) U3.AA19(HPIO8_4B/DP1_DQSN4)
FMC2_LA23_P: J54.D23(LA23_P) U3.AB19(HPIO8_4A/DP1_DQS4)
FMC2_LA24_N: J54.H29(LA24_N) U3.AG24(HPIO8_16B/DP1_DQ25)
FMC2_LA24_P: J54.H28(LA24_P) U3.AG23(HPIO8_16A/DP1_DQ24)
FMC2_LA25_N: J54.G28(LA25_N) U3.AH23(HPIO8_22B/DP1_DQ27)
FMC2_LA25_P: J54.G27(LA25_P) U3.AJ23(HPIO8_22A/DP1_DQ26)
FMC2_LA26_N: J54.D27(LA26_N) U3.AA20(HPIO8_2B/DP1_DQ33)
FMC2_LA26_P: J54.D26(LA26_P) U3.Y20(HPIO8_2A/DP1_DQ32)
FMC2_LA27_N: J54.C27(LA27_N) U3.AP27(HPIO8_15B/DP1_MCLKC3)
FMC2_LA27_P: J54.C26(LA27_P) U3.AP28(HPIO8_15A/DP1_MCLKT3)
FMC2_LA28_N: J54.H32(LA28_N) U3.AL25(HPIO8_1B/DP1_DQ21)
FMC2_LA28_P: J54.H31(LA28_P) U3.AK25(HPIO8_1A/DP1_DQ20)
FMC2_LA29_N: J54.G31(LA29_N) U3.AH25(HPIO8_20B/DP1_DQ31)
FMC2_LA29_P: J54.G30(LA29_P) U3.AH24(HPIO8_20A/DP1_DQ30)
FMC2_LA30_N: J54.H35(LA30_N) U3.AL28(HPIO8_7B/DP1_DQ23)
FMC2_LA30_P: J54.H34(LA30_P) U3.AL27(HPIO8_7A/DP1_DQ22)
FMC2_LA31_N: J54.G34(LA31_N) U3.AF25(HPIO8_14B/DP1_DQ29)
FMC2_LA31_P: J54.G33(LA31_P) U3.AG25(HPIO8_14A/DP1_DQ28)
FMC2_LA32_N: J54.H38(LA32_N) U3.AM29(HPIO8_9B/DP1_DQ19)
FMC2_LA32_P: J54.H37(LA32_P) U3.AL29(HPIO8_9A/DP1_DQ18)
FMC2_LA33_N: J54.G37(LA33_N) U3.AK27(HPIO8_5B/DP1_DQSN2)
FMC2_LA33_P: J54.G36(LA33_P) U3.AK28(HPIO8_5A/DP1_DQS2)
FMC2_PG_C2M: J53.4 J54.D1(PG_C2M) R327.1 U3.T18(WRIO13_2A)
FMC2_PG_M2C: J53.5 J54.F1(PG_M2C) R328.1 U3.T19(WRIO13_2B)
FMC2_PRSNT_M2C_L: J53.8 J54.H2(PRSNT_M2C_L) R310.1 U3.T15(WRIO13_3A)
FMC2_RES0: R309.2 U3.R19(WRIO13_0A)
FMC2_RES1: R308.2 U3.R18(WRIO13_0B)
FMC2_SCL: J53.10 J54.C30(SCL) R321.1 U3.R15(WRIO13_1B)
FMC2_SDA: J53.14 J54.C31(SDA) R322.1 U3.R14(WRIO13_1A)
FMC2_TCK: J53.3 J54.D29(TCK) R317.1 R345.1
FMC2_TDI: J53.7 J54.D30(TDI) R314.1 U3.U16(WRIO13_4A)
FMC2_TDO: J53.9 J54.D31(TDO) R315.1 U3.U17(WRIO13_4B)
